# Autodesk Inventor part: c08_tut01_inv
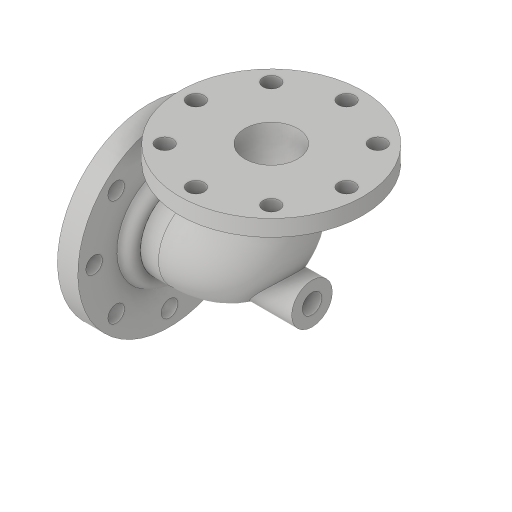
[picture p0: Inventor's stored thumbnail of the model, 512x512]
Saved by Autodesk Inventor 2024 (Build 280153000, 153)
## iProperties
Created: 2015-03
Part Number: c08_tut01_inv
Material: Generic
Document SubType Name: Modeling
Designer: Sandeep
Density: 1 g/cm^3
Appearance: Default
Author: Sandeep
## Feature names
1. Sweep1
2. Shell1
3. Extrusion1
4. Extrusion2
5. Extrusion3
6. Extrusion4
7. Fillet1
8. Extrusion5
9. Circular Pattern1
10. Extrusion6
11. Circular Pattern2
12. Extrusion7
13. Hole1
## Parameters: d1 = 35 mm, d2 = 35 mm, d4 = 97 mm, d5 = 0, d6 = 0, d7 = 16 mm, d8 = 225 mm, d10 = 0, d11 = 225 mm, d13 = 25 mm, d14 = 0, d15 = 86 mm, d16 = 22 mm, d17 = 0, d18 = 129 mm, d19 = 16 mm, d20 = 0, d21 = 16 mm, d22 = 185 mm, d23 = 20.5 mm, d24 = 0, d25 = 0, d27 = 360 deg, d29 = 185 mm, d30 = 20.5 mm, d31 = 16 mm, d32 = 0, d34 = 360 deg, d37 = 175 mm, d39 = 145 mm, d40 = 16 mm, d41 = 0, d45 = 6 mm, d46 = 24 mm, d47 = 28 mm, d48 = 90 deg, d49 = 8 mm, d50 = 118 deg
